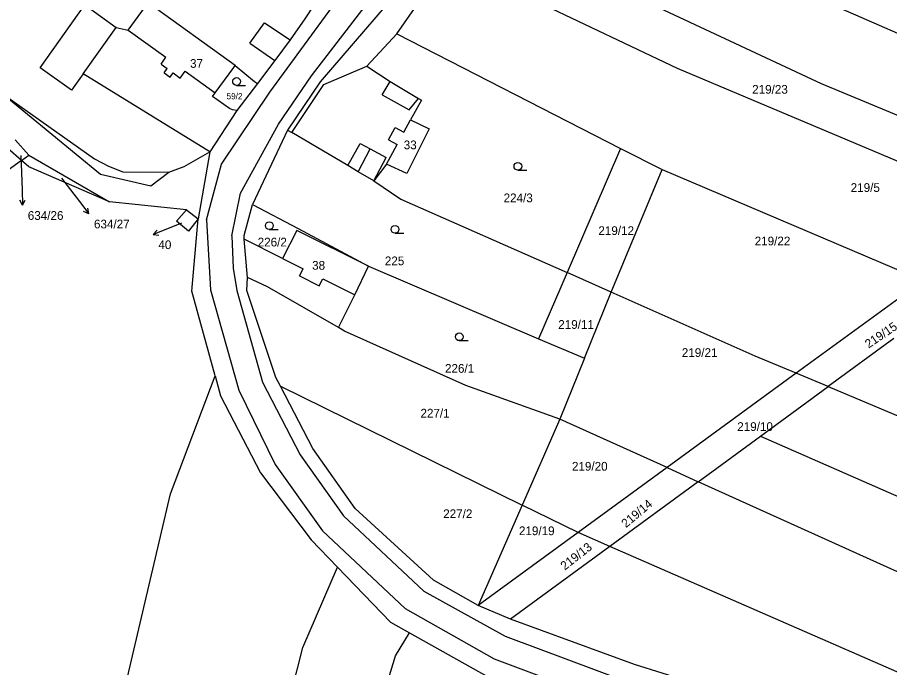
# Model space of a CAD drawing. Extents: x -746176 to -739709, y -1128407 to -1124482.
# Drawn here: x -743087.7 to -742917.8, y -1127796.2 to -1127669.6 of the extents above; entities that cross this region are included whole.
import ezdxf

# ---------------------------------------------------------------- set-up
doc = ezdxf.new("R2010")
doc.units = 0
for name, color, linetype in [('Vrstva 33', 7, 'Continuous'), ('Vrstva 42', 7, 'Continuous'), ('Vrstva 43', 7, 'Continuous'), ('Vrstva 44', 7, 'Continuous'), ('Vrstva 47', 7, 'Continuous')]:
    doc.layers.add(name, color=color, linetype=linetype)

msp = doc.modelspace()

# ---------------------------------------------------------------- linework, layer by layer
at = {"layer": 'Vrstva 33'}
for p, q in [((-743013.81, -1127672.8), (-743003.07, -1127657.38)), ((-743045.29, -1127678.95), (-743062.24, -1127666.73)), ((-743019.62, -1127679.08), (-743013.81, -1127672.8)), ((-743013.81, -1127672.8), (-742970.18, -1127695.1)), ((-743040.96, -1127682.5), (-743044.97, -1127687.73)), ((-743044.97, -1127687.73), (-743050.26, -1127695.79)), ((-743035.1, -1127691.53), (-743041.92, -1127706.05)), ((-743035.1, -1127691.53), (-743034.24, -1127692.03)), ((-743088.2, -1127693.47), (-743085.48, -1127696.45)), ((-743086.91, -1127697.47), (-743089.62, -1127695.12)), ((-743050.26, -1127695.79), (-743052.52, -1127708.86)), ((-742970.18, -1127695.1), (-742980.63, -1127719.3)), ((-742970.18, -1127695.1), (-742962.09, -1127699.23)), ((-743086.91, -1127697.47), (-743085.48, -1127696.45)), ((-743085.48, -1127696.45), (-743069.79, -1127705.5)), ((-742972.01, -1127723.11), (-742962.09, -1127699.23)), ((-742962.09, -1127699.23), (-742911.19, -1127720.85)), ((-743054.75, -1127707.06), (-743069.79, -1127705.5)), ((-743054.75, -1127707.06), (-743052.52, -1127708.86)), ((-743042.89, -1127720.23), (-743043.57, -1127712.76)), ((-743019.3, -1127718.08), (-742986.19, -1127732.18)), ((-742980.63, -1127719.3), (-742986.19, -1127732.18)), ((-742972.01, -1127723.11), (-742980.63, -1127719.3)), ((-742911.19, -1127720.85), (-742935.96, -1127738.92)), ((-742977.22, -1127736), (-742972.01, -1127723.11)), ((-742986.19, -1127732.18), (-742977.22, -1127736)), ((-742916.95, -1127732.14), (-742929.76, -1127741.52)), ((-742977.22, -1127736), (-742982, -1127747.83)), ((-742935.96, -1127738.92), (-742961.12, -1127757.28)), ((-742929.76, -1127741.52), (-742935.96, -1127738.92)), ((-743036.47, -1127741.45), (-742989.35, -1127764.58)), ((-742942.9, -1127751.14), (-742929.76, -1127741.52)), ((-742982, -1127747.83), (-742989.35, -1127764.58)), ((-742961.12, -1127757.28), (-742982, -1127747.83)), ((-742955.04, -1127760.03), (-742942.9, -1127751.14)), ((-742961.12, -1127757.28), (-742978.46, -1127769.93)), ((-742961.12, -1127757.28), (-742955.04, -1127760.03)), ((-742955.04, -1127760.03), (-742972.27, -1127772.64)), ((-742989.35, -1127764.58), (-742997.92, -1127784.13)), ((-742978.46, -1127769.93), (-742989.35, -1127764.58)), ((-742978.46, -1127769.93), (-742997.92, -1127784.13)), ((-742972.27, -1127772.64), (-742978.46, -1127769.93)), ((-742972.27, -1127772.64), (-742991.64, -1127786.82)), ((-742833.19, -1127833.4), (-742972.27, -1127772.64)), ((-742991.64, -1127786.82), (-742997.92, -1127784.13)), ((-743011.33, -1127789.48), (-742996.28, -1127797.93))]:
    msp.add_line(p, q, dxfattribs=at)
for points in [[(-742984.29, -1127611.5), (-742990.11, -1127623.65), (-743005.02, -1127654.54), (-743028.72, -1127682.17), (-743035.1, -1127691.53)], [(-742989.43, -1127637.82), (-742962.79, -1127651.94), (-742947.37, -1127659.01), (-742888.66, -1127684.65), (-742875.08, -1127689.31), (-742869.86, -1127690.69)], [(-742884.93, -1127701.69), (-742931.01, -1127682.52), (-742982.33, -1127658.51), (-742997.69, -1127649.67)], [(-742892.82, -1127707.45), (-742959.07, -1127679.57), (-742986.2, -1127666.67), (-743003.07, -1127657.38)], [(-743026.2, -1127661.44), (-743031.72, -1127669.85), (-743034.56, -1127673.98), (-743037.58, -1127678), (-743040.96, -1127682.5)], [(-743050.26, -1127695.79), (-743074.95, -1127680.59), (-743077.21, -1127683.74), (-743083.3, -1127679.41), (-743074.6, -1127667.14), (-743068.46, -1127671.55), (-743066.13, -1127672.07), (-743062.24, -1127666.73)], [(-743044.97, -1127687.73), (-743045.79, -1127687.59), (-743046.39, -1127687.31), (-743049.72, -1127685.03), (-743049.19, -1127684.3), (-743045.58, -1127679.36), (-743045.29, -1127678.95)], [(-743045.29, -1127678.95), (-743041.53, -1127682.11), (-743040.96, -1127682.5)], [(-743034.24, -1127692.03), (-743027.99, -1127682.66), (-743019.62, -1127679.08)], [(-743019.62, -1127679.08), (-743015.08, -1127682.06), (-743009.56, -1127685.38), (-743009, -1127685.72), (-743011.13, -1127689.55), (-743007.52, -1127691.27), (-743011.82, -1127700.03), (-743015.78, -1127698.17), (-743018.27, -1127701.4)], [(-743090.48, -1127684.56), (-743071.53, -1127700.11), (-743061.74, -1127702.4), (-743058.22, -1127699.76)], [(-743018.27, -1127701.4), (-743021.3, -1127699.65), (-743023.34, -1127698.47), (-743034.24, -1127692.03)], [(-743058.22, -1127699.76), (-743055.21, -1127698.61), (-743050.26, -1127695.79)], [(-743086.91, -1127697.47), (-743090.95, -1127700.36), (-743100.45, -1127723.29), (-743120.32, -1127804.45), (-743137.57, -1127875.6)], [(-743069.79, -1127705.5), (-743085.49, -1127698.7), (-743086.91, -1127697.47)], [(-743018.27, -1127701.4), (-743013, -1127704.97), (-742980.63, -1127719.3)], [(-743043.57, -1127712.76), (-743043.55, -1127712.08), (-743041.92, -1127706.05)], [(-743041.92, -1127706.05), (-743033.05, -1127710.69), (-743019.3, -1127718.08)], [(-743052.52, -1127708.86), (-743054.42, -1127711.2), (-743056.75, -1127709.3), (-743054.75, -1127707.06)], [(-743049.21, -1127739.41), (-743053.72, -1127722.94), (-743052.52, -1127708.86)], [(-743019.3, -1127718.08), (-743033.26, -1127711.09), (-743036.05, -1127716.56), (-743043.57, -1127712.76)], [(-743025.14, -1127730.02), (-743022, -1127723.61), (-743019.3, -1127718.08)], [(-743036.47, -1127741.45), (-743037.36, -1127739.74), (-743043.04, -1127722.81), (-743042.89, -1127720.23)], [(-743025.14, -1127730.02), (-743039.01, -1127722.1), (-743042.89, -1127720.23)], [(-742935.96, -1127738.92), (-742943.98, -1127735.55), (-742972.01, -1127723.11)], [(-742982, -1127747.83), (-743000.34, -1127741.31), (-743023.98, -1127730.68), (-743025.14, -1127730.02)], [(-743134.48, -1128101.6), (-743116.84, -1128032.47), (-743112.87, -1128006.6), (-743093.99, -1127930.3), (-743081.3, -1127862.06), (-743057.88, -1127762.39), (-743049.21, -1127739.41)], [(-743049.21, -1127739.41), (-743048.14, -1127743.3), (-743040.35, -1127758.3), (-743030.5, -1127771.33), (-743025.38, -1127776.65)], [(-742997.92, -1127784.13), (-743006.65, -1127779.24), (-743021.89, -1127765.25), (-743030.16, -1127753.57), (-743036.47, -1127741.45)], [(-742929.76, -1127741.52), (-742892.25, -1127757.26), (-742839.56, -1127779.37), (-742839.56, -1127777.92), (-742777.16, -1127805.95), (-742712.92, -1127837.01)], [(-742942.9, -1127751.14), (-742921.78, -1127760.46), (-742847.12, -1127793.15), (-742812.02, -1127809), (-742724.3, -1127849.19), (-742701.43, -1127856.81), (-742666.84, -1127871.89)], [(-742670.28, -1127883.77), (-742733.59, -1127858.01), (-742796.71, -1127830.89), (-742912.22, -1127779.41), (-742955.04, -1127760.03)], [(-743103, -1128100.87), (-743064.96, -1127935.44), (-743045.29, -1127844.24), (-743032.09, -1127792.31), (-743025.38, -1127776.65)], [(-743025.38, -1127776.65), (-743015.05, -1127787.39), (-743011.33, -1127789.48)], [(-742830.43, -1127861.03), (-742831.55, -1127859.78), (-742848.33, -1127844.01), (-742864.61, -1127832.85), (-742882.56, -1127824.07), (-742889.66, -1127821.18), (-742902.77, -1127815.89), (-742967.48, -1127795.61), (-742991.64, -1127786.82)], [(-743087.22, -1128100.5), (-743078.12, -1128059.75), (-743051.52, -1127944.14), (-743026.17, -1127833.83), (-743014.07, -1127793.96), (-743011.33, -1127789.48)]]:
    msp.add_lwpolyline(points, dxfattribs=at)
at = {"layer": 'Vrstva 43'}
for p, q in [((-743087.06, -1127696.52), (-743086.82, -1127703.2)), ((-743079.13, -1127700.88), (-743075.63, -1127705.47)), ((-743086.82, -1127703.2), (-743086.71, -1127706.2)), ((-743086.71, -1127706.2), (-743087.25, -1127705.22)), ((-743086.71, -1127706.2), (-743086.25, -1127705.18)), ((-743075.63, -1127705.47), (-743073.82, -1127707.87)), ((-743073.82, -1127707.87), (-743074.83, -1127707.37)), ((-743073.82, -1127707.87), (-743074.03, -1127706.77)), ((-743055.74, -1127709.69), (-743058.47, -1127710.78)), ((-743058.47, -1127710.78), (-743061.25, -1127711.9)), ((-743061.25, -1127711.9), (-743060.51, -1127711.06)), ((-743061.25, -1127711.9), (-743060.14, -1127711.99))]:
    msp.add_line(p, q, dxfattribs=at)
at = {"layer": 'Vrstva 44'}
for p, q in [((-743045.03, -1127682.83), (-743043.28, -1127682.83)), ((-742990.21, -1127699.35), (-742988.46, -1127699.35)), ((-743038.64, -1127710.9), (-743036.89, -1127710.9)), ((-743014.15, -1127711.62), (-743012.4, -1127711.62)), ((-743001.63, -1127732.56), (-742999.88, -1127732.56))]:
    msp.add_line(p, q, dxfattribs=at)
for centre in [(-743045.03, -1127682.08), (-742990.21, -1127698.6), (-743038.64, -1127710.15), (-743014.15, -1127710.87), (-743001.63, -1127731.81)]:
    msp.add_circle(centre, 0.75, dxfattribs=at)
at = {"layer": 'Vrstva 47'}
for p, q in [((-743030.45, -1127680.95), (-743007.93, -1127651.85)), ((-743038.55, -1127684.18), (-743020.57, -1127659.55)), ((-743042.45, -1127674.62), (-743039.6, -1127670.68)), ((-743039.6, -1127670.68), (-743034.56, -1127673.98)), ((-743074.95, -1127680.59), (-743068.46, -1127671.55)), ((-743066.13, -1127672.07), (-743058.8, -1127677.37)), ((-743042.45, -1127674.62), (-743037.58, -1127678)), ((-743059.75, -1127678.69), (-743058.8, -1127677.37)), ((-743059.75, -1127678.69), (-743058.57, -1127679.56)), ((-743059.15, -1127680.38), (-743058.57, -1127679.56)), ((-743059.15, -1127680.38), (-743057.98, -1127681.22)), ((-743057.98, -1127681.22), (-743057.39, -1127680.41)), ((-743057.39, -1127680.41), (-743056.02, -1127681.41)), ((-743056.02, -1127681.41), (-743055.05, -1127680.07)), ((-743055.05, -1127680.07), (-743049.19, -1127684.3)), ((-743036.85, -1127690.37), (-743030.45, -1127680.95)), ((-743016.62, -1127684.69), (-743015.08, -1127682.06)), ((-743047.98, -1127698.19), (-743038.55, -1127684.18)), ((-743090.48, -1127684.56), (-743072.72, -1127697.13)), ((-743016.62, -1127684.69), (-743011.36, -1127687.63)), ((-743011.36, -1127687.63), (-743009.56, -1127685.38)), ((-743044.25, -1127703.82), (-743036.85, -1127690.37)), ((-743015.4, -1127693.46), (-743014.15, -1127691.05)), ((-743014.15, -1127691.05), (-743012.44, -1127691.97)), ((-743012.44, -1127691.97), (-743011.13, -1127689.55)), ((-743023.34, -1127698.47), (-743020.92, -1127694.17)), ((-743020.92, -1127694.17), (-743018.97, -1127695.22)), ((-743015.78, -1127698.17), (-743013.73, -1127694.36)), ((-743015.4, -1127693.46), (-743013.73, -1127694.36)), ((-743021.3, -1127699.65), (-743018.97, -1127695.22)), ((-743018.97, -1127695.22), (-743015.9, -1127696.88)), ((-743072.72, -1127697.13), (-743070.01, -1127698.54)), ((-743018.27, -1127701.4), (-743015.9, -1127696.88)), ((-743070.01, -1127698.54), (-743067.17, -1127699.66)), ((-743067.17, -1127699.66), (-743058.22, -1127699.76)), ((-743050.88, -1127709.04), (-743047.98, -1127698.19)), ((-743045.96, -1127712.14), (-743044.25, -1127703.82)), ((-743050.88, -1127709.04), (-743050.12, -1127722.67)), ((-743045.96, -1127712.14), (-743045.67, -1127718.43)), ((-743036.05, -1127716.56), (-743032.05, -1127718.56)), ((-743045.67, -1127718.43), (-743044.96, -1127722.78)), ((-743032.75, -1127719.95), (-743032.05, -1127718.56)), ((-743032.75, -1127719.95), (-743028.9, -1127721.9)), ((-743028.9, -1127721.9), (-743028.19, -1127720.5)), ((-743028.19, -1127720.5), (-743022, -1127723.61)), ((-743050.12, -1127722.67), (-743044.56, -1127742.19)), ((-743044.96, -1127722.78), (-743039.98, -1127740.62)), ((-743044.56, -1127742.19), (-743037.53, -1127756.7)), ((-743039.98, -1127740.62), (-743032.62, -1127754.77)), ((-743032.62, -1127754.77), (-743024.19, -1127766.7)), ((-743037.53, -1127756.7), (-743028.31, -1127769.6)), ((-743024.19, -1127766.7), (-743008.52, -1127781.37)), ((-743028.31, -1127769.6), (-743012.17, -1127784.72)), ((-743008.52, -1127781.37), (-742992.69, -1127790.12)), ((-743012.17, -1127784.72), (-742994.83, -1127794.53)), ((-742992.69, -1127790.12), (-742968.49, -1127799.16)), ((-742994.83, -1127794.53), (-742969.96, -1127803.78))]:
    msp.add_line(p, q, dxfattribs=at)

# ---------------------------------------------------------------- texts
at = {"layer": 'Vrstva 42'}
for s, height, p in [('37', 1.7, (-743054.09, -1127679.41)), ('219/23', 1.7, (-742944.55, -1127684.46)), ('59/2', 1.19, (-743046.97, -1127685.54)), ('33', 1.7, (-743012.45, -1127695.28)), ('219/5', 1.7, (-742925.35, -1127703.59)), ('224/3', 1.7, (-742992.99, -1127705.6)), ('634/26', 1.7, (-743085.71, -1127709.03)), ('634/27', 1.7, (-743072.81, -1127710.69)), ('219/12', 1.7, (-742974.52, -1127711.98)), ('40', 1.7, (-743060.26, -1127714.72)), ('226/2', 1.7, (-743040.91, -1127714.21)), ('219/22', 1.7, (-742944.06, -1127714)), ('225', 1.7, (-743016.13, -1127717.87)), ('38', 1.7, (-743030.3, -1127718.74)), ('219/11', 1.7, (-742982.34, -1127730.26)), ('219/21', 1.7, (-742958.26, -1127735.73)), ('226/1', 1.7, (-743004.41, -1127738.81)), ('227/1', 1.7, (-743009.19, -1127747.54)), ('219/10', 1.7, (-742947.46, -1127750.15)), ('219/20', 1.7, (-742979.67, -1127757.88)), ('227/2', 1.7, (-743004.76, -1127767.12)), ('219/19', 1.7, (-742990, -1127770.44))]:
    msp.add_text(s, height=height, dxfattribs=at).set_placement(p)
for s, rotation, p in [('219/15', 34, (-742921.86, -1127734.11)), ('219/14', 40, (-742969.15, -1127769.1)), ('219/13', 38, (-742981.07, -1127777.36))]:
    msp.add_text(s, height=1.7, rotation=rotation, dxfattribs=at).set_placement(p)

doc.saveas('drawing.dxf')
